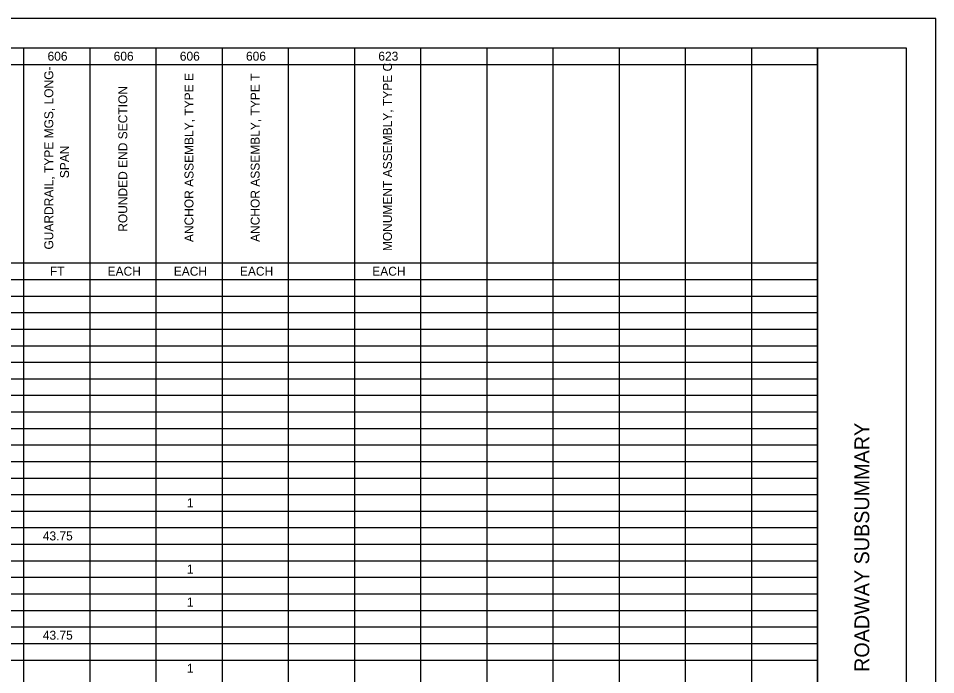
# Model space of a CAD drawing. Extents: x -0.1 to 36.2, y 0 to 22.
# Drawn here: x 18.34 to 33.88, y 10.87 to 21.98 of the extents above; entities that cross this region are included whole.
import ezdxf

# ---------------------------------------------------------------- set-up
doc = ezdxf.new("R2010")
doc.units = 0
for name, color, linetype in [('SH_Border', 7, 'Continuous'), ('SH_Cut_Line', 7, 'Continuous'), ('SH_Data', 7, 'Continuous'), ('SH_Text', 7, 'Continuous')]:
    doc.layers.add(name, color=color, linetype=linetype)

msp = doc.modelspace()

# ---------------------------------------------------------------- linework, layer by layer
at = {"layer": 'SH_Border'}
msp.add_line((31.876, 0.475), (31.876, 21.475), dxfattribs=at)
msp.add_lwpolyline([(1.376, 21.475), (33.376, 21.475), (33.376, 0.475), (1.376, 0.475)], close=True, dxfattribs=at)
at = {"layer": 'SH_Cut_Line'}
msp.add_lwpolyline([(-0.124, -0.025), (33.876, -0.025), (33.876, 21.975), (-0.124, 21.975)], close=True, dxfattribs=at)
at = {"layer": 'SH_Text'}
for p, q in [((1.376, 21.475), (31.876, 21.475)), ((18.43, 21.475), (18.43, 0.475)), ((19.55, 21.475), (19.55, 0.475)), ((20.671, 21.475), (20.671, 0.475)), ((21.791, 21.475), (21.791, 0.475)), ((22.912, 21.475), (22.912, 0.475)), ((24.032, 21.475), (24.032, 0.475)), ((25.153, 21.475), (25.153, 0.475)), ((26.273, 21.475), (26.273, 0.475)), ((27.394, 21.475), (27.394, 0.475)), ((28.514, 21.475), (28.514, 0.475)), ((29.635, 21.475), (29.635, 0.475)), ((30.755, 21.475), (30.755, 0.475)), ((31.876, 21.475), (31.876, 0.475)), ((9.466, 21.195), (31.876, 21.195)), ((8.346, 17.835), (31.876, 17.835)), ((1.376, 17.555), (31.876, 17.555)), ((1.376, 17.275), (31.876, 17.275)), ((1.376, 16.995), (31.876, 16.995)), ((1.376, 16.715), (31.876, 16.715)), ((1.376, 16.435), (31.876, 16.435)), ((1.376, 16.155), (31.876, 16.155)), ((1.376, 15.875), (31.876, 15.875)), ((1.376, 15.595), (31.876, 15.595)), ((1.376, 15.315), (31.876, 15.315)), ((1.376, 15.035), (31.876, 15.035)), ((1.376, 14.755), (31.876, 14.755)), ((1.376, 14.475), (31.876, 14.475)), ((1.376, 14.195), (31.876, 14.195)), ((1.376, 13.915), (31.876, 13.915)), ((1.376, 13.635), (31.876, 13.635)), ((1.376, 13.355), (31.876, 13.355)), ((1.376, 13.075), (31.876, 13.075)), ((1.376, 12.795), (31.876, 12.795)), ((1.376, 12.515), (31.876, 12.515)), ((1.376, 12.235), (31.876, 12.235)), ((1.376, 11.955), (31.876, 11.955)), ((1.376, 11.675), (31.876, 11.675)), ((1.376, 11.395), (31.876, 11.395)), ((1.376, 11.115), (31.876, 11.115))]:
    msp.add_line(p, q, dxfattribs=at)

# ---------------------------------------------------------------- texts
at = {"layer": 'SH_Data'}
msp.add_text('ROADWAY SUBSUMMARY', height=0.25, rotation=90, dxfattribs=at).set_placement((32.751, 10.913))
at = {"layer": 'SH_Text'}
for s, height, p in [('606', 0.1515, (18.836, 21.259)), ('606', 0.1515, (19.956, 21.259)), ('606', 0.1515, (21.076, 21.259)), ('606', 0.1515, (22.197, 21.259)), ('623', 0.1515, (24.438, 21.259)), ('FT', 0.1515, (18.876, 17.619)), ('EACH', 0.1515, (19.853, 17.619)), ('EACH', 0.1515, (20.974, 17.619)), ('EACH', 0.1515, (22.094, 17.619)), ('EACH', 0.1515, (24.335, 17.619)), ('1', 0.152, (21.196, 13.699)), ('43.75', 0.1515, (18.756, 13.139)), ('1', 0.152, (21.196, 12.579)), ('1', 0.152, (21.196, 12.019)), ('43.75', 0.1515, (18.756, 11.459)), ('1', 0.152, (21.196, 10.899))]:
    msp.add_text(s, height=height, dxfattribs=at).set_placement(p)
for s, height, p in [('GUARDRAIL, TYPE MGS, LONG-', 0.15159, (18.933, 18.062)), ('MONUMENT ASSEMBLY, TYPE C', 0.15159, (24.668, 18.035)), ('ANCHOR ASSEMBLY, TYPE E', 0.15159, (21.307, 18.188)), ('ANCHOR ASSEMBLY, TYPE T', 0.15159, (22.427, 18.191)), ('ROUNDED END SECTION', 0.15159, (20.186, 18.363)), ('SPAN', 0.1516, (19.199, 19.27))]:
    msp.add_text(s, height=height, rotation=90, dxfattribs=at).set_placement(p)

doc.saveas('drawing.dxf')
